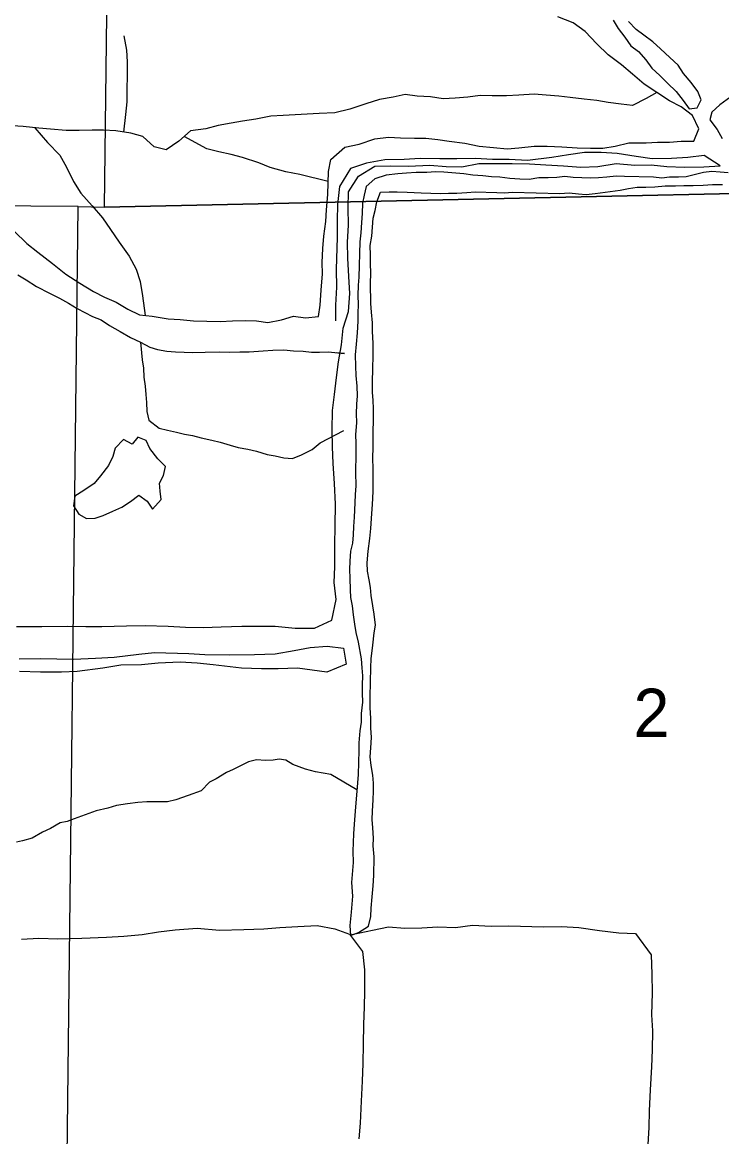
# Model space of a CAD drawing. Extents: x 0 to 34, y 0 to 22.
# Drawn here: x 2.2397 to 2.5423, y 15.0235 to 15.5055 of the extents above; entities that cross this region are included whole.
import ezdxf

# ---------------------------------------------------------------- set-up
doc = ezdxf.new("R2010")
doc.units = 0
for name, color, linetype in [('GM_X_Corporation', 7, 'Continuous'), ('GM_X_Minor_Lake', 7, 'Continuous'), ('GM_X_Minor_River', 7, 'Continuous'), ('GM_X_Section_Text', 7, 'Continuous')]:
    doc.layers.add(name, color=color, linetype=linetype)

msp = doc.modelspace()

# ---------------------------------------------------------------- linework, layer by layer
at = {"layer": 'GM_X_Corporation'}
for points in [[(2.28152, 15.93664), (2.79079, 15.94235), (2.78571, 15.43693), (2.76751, 15.43626), (2.27529, 15.42554)], [(2.76751, 15.43626), (2.75917, 15.00116), (2.25879, 14.98955), (2.26391, 15.42579), (2.27529, 15.42554)], [(2.1, 15.42693), (2.1, 14.98485), (2.25879, 14.98955), (2.26391, 15.42579)]]:
    msp.add_lwpolyline(points, close=True, dxfattribs=at)
at = {"layer": 'GM_X_Minor_Lake'}
for points in [[(2.28728, 15.32308), (2.28343, 15.32504), (2.27991, 15.32134), (2.27886, 15.31776), (2.27704, 15.31383), (2.27349, 15.30937), (2.27074, 15.30603), (2.26629, 15.30293), (2.26242, 15.30057), (2.26193, 15.2964), (2.2641, 15.29273), (2.26746, 15.29093), (2.27126, 15.29101), (2.27472, 15.29224), (2.27894, 15.29401), (2.28279, 15.2958), (2.28647, 15.29817), (2.29015, 15.30091), (2.29368, 15.29834), (2.29605, 15.29485), (2.29978, 15.29911), (2.29932, 15.30274), (2.29903, 15.30616), (2.30084, 15.30953), (2.3017, 15.31331), (2.29838, 15.31663), (2.2949, 15.3211), (2.29329, 15.32457)], [(2.29329, 15.32457), (2.28973, 15.326), (2.28728, 15.32308)]]:
    msp.add_lwpolyline(points, dxfattribs=at)
at = {"layer": 'GM_X_Minor_River'}
for points in [[(2.51419, 15.47513), (2.50879, 15.4787), (2.50379, 15.48303), (2.49897, 15.48715), (2.49321, 15.4915), (2.48822, 15.4962), (2.48324, 15.50148), (2.47803, 15.50524), (2.47146, 15.5079)], [(2.49534, 15.50645), (2.49752, 15.50278), (2.50045, 15.49908), (2.503, 15.4954), (2.50634, 15.49283), (2.50947, 15.48932), (2.51202, 15.48564), (2.51554, 15.4825), (2.51886, 15.47917), (2.52256, 15.47564), (2.52568, 15.47175), (2.52823, 15.46807), (2.53166, 15.46854), (2.53347, 15.47191), (2.53205, 15.47556), (2.52912, 15.47945), (2.52582, 15.48334), (2.52346, 15.48702), (2.51994, 15.49035), (2.51587, 15.49408), (2.51254, 15.49702), (2.50864, 15.49998), (2.50529, 15.50236), (2.50197, 15.50588)], [(2.28366, 15.49963), (2.28481, 15.49352), (2.28505, 15.48838), (2.28505, 15.48192), (2.28491, 15.47699), (2.28493, 15.4711), (2.2844, 15.4656), (2.28345, 15.45803)], [(2.2749, 15.45885), (2.26997, 15.4588), (2.26427, 15.45877), (2.25876, 15.45874), (2.25195, 15.45932), (2.24683, 15.45966), (2.24002, 15.46042), (2.233, 15.46082), (2.22696, 15.46175), (2.22186, 15.46266), (2.21693, 15.46318), (2.2107, 15.46412), (2.20503, 15.46504), (2.20016, 15.46746), (2.1969, 15.47287), (2.19514, 15.47787), (2.1951, 15.483), (2.2002, 15.48874), (2.20681, 15.48779), (2.21223, 15.48478), (2.21437, 15.47978), (2.21516, 15.47425), (2.21973, 15.4626)], [(2.28038, 15.3844), (2.28542, 15.38141), (2.29048, 15.37898), (2.29597, 15.37845), (2.30277, 15.3773), (2.30807, 15.37696), (2.31375, 15.37641), (2.32532, 15.37608), (2.33065, 15.37631), (2.33616, 15.37653), (2.34109, 15.37638), (2.34601, 15.37567), (2.35192, 15.37683), (2.35709, 15.37839), (2.3622, 15.37768), (2.36791, 15.37827), (2.36862, 15.38319), (2.369, 15.38964), (2.36957, 15.39665), (2.36952, 15.40159), (2.3697, 15.40767), (2.37023, 15.41297), (2.37098, 15.41941), (2.37131, 15.42434), (2.37188, 15.43097), (2.37217, 15.44103), (2.37326, 15.44613), (2.3793, 15.45147), (2.38541, 15.45281), (2.39231, 15.45508), (2.39822, 15.45586), (2.40333, 15.45552), (2.40941, 15.45535), (2.41434, 15.4554), (2.41945, 15.45487), (2.42437, 15.45416), (2.43118, 15.4532), (2.4374, 15.45188), (2.44365, 15.45132), (2.44952, 15.45077), (2.45447, 15.4512), (2.46114, 15.45196), (2.46683, 15.45198), (2.47309, 15.45161), (2.47972, 15.45123), (2.4856, 15.45106), (2.49092, 15.4511), (2.49626, 15.45189), (2.50218, 15.45343), (2.50959, 15.45341), (2.51453, 15.45365), (2.51966, 15.45369), (2.5248, 15.45411), (2.5303, 15.45414), (2.53235, 15.4594), (2.52967, 15.46518), (2.52484, 15.46893), (2.51979, 15.47154), (2.51419, 15.47513), (2.50957, 15.4726), (2.50378, 15.46954), (2.49886, 15.47006), (2.49319, 15.47079), (2.48828, 15.47169), (2.48279, 15.47223), (2.47673, 15.47298), (2.47181, 15.4735), (2.46632, 15.47404), (2.4612, 15.47437), (2.45455, 15.474), (2.44923, 15.47377), (2.44296, 15.47376), (2.43784, 15.47391), (2.4325, 15.47311), (2.42698, 15.4727), (2.42185, 15.47247), (2.41637, 15.4732), (2.41049, 15.47356), (2.40539, 15.47427), (2.40023, 15.47309), (2.39432, 15.47212), (2.38838, 15.4702), (2.38148, 15.46793), (2.37498, 15.46641), (2.36813, 15.46604), (2.36034, 15.46569), (2.35254, 15.46516), (2.34722, 15.46493), (2.34073, 15.4636), (2.33501, 15.46281), (2.33004, 15.46182), (2.32451, 15.46084), (2.31916, 15.45947), (2.31248, 15.45852), (2.30742, 15.45411), (2.302, 15.45028), (2.29672, 15.45157), (2.29191, 15.45608), (2.28664, 15.45756), (2.28021, 15.4585), (2.2749, 15.45885)], [(2.54622, 15.47325), (2.54157, 15.46978), (2.53806, 15.46665), (2.53721, 15.46325), (2.54032, 15.45917), (2.54248, 15.45531)], [(2.24513, 15.45985), (2.25064, 15.45347), (2.25599, 15.44799), (2.25888, 15.44278), (2.26193, 15.43661), (2.26501, 15.43158), (2.26999, 15.42612), (2.27439, 15.42086), (2.27786, 15.41582), (2.28169, 15.41039), (2.28588, 15.40438), (2.28895, 15.39879), (2.2907, 15.39342), (2.29166, 15.38712), (2.29283, 15.37875)], [(2.37204, 15.4367), (2.35979, 15.43968), (2.35375, 15.4408), (2.34697, 15.44271), (2.34209, 15.44475), (2.33494, 15.44705), (2.33004, 15.44833), (2.32475, 15.44943), (2.31948, 15.45072), (2.30974, 15.45613)], [(2.50475, 15.44367), (2.51178, 15.44385), (2.5186, 15.44308), (2.52618, 15.44286), (2.53454, 15.443), (2.54158, 15.44337), (2.53468, 15.44794), (2.52763, 15.447), (2.5206, 15.44663), (2.51224, 15.44649), (2.50524, 15.44746), (2.49712, 15.44883), (2.49011, 15.44922), (2.48289, 15.44924), (2.47602, 15.44811), (2.46878, 15.44699), (2.4583, 15.44577), (2.45034, 15.44619), (2.44313, 15.44621), (2.43573, 15.44661), (2.42776, 15.44646), (2.42035, 15.44648), (2.41181, 15.44654), (2.40497, 15.44617), (2.39661, 15.44603), (2.38859, 15.44455), (2.38169, 15.44228), (2.37691, 15.43444), (2.37612, 15.42667), (2.37593, 15.41984), (2.37591, 15.41262), (2.37551, 15.39857), (2.37568, 15.39097), (2.37527, 15.38319), (2.37526, 15.37635)], [(2.23727, 15.24411), (2.2481, 15.24418), (2.2593, 15.24424), (2.26727, 15.2442), (2.27411, 15.24419), (2.28475, 15.24445), (2.29291, 15.2446), (2.30278, 15.24431), (2.31036, 15.2439), (2.31795, 15.24369), (2.32574, 15.24403), (2.33467, 15.24434), (2.3491, 15.24431), (2.35781, 15.24349), (2.36616, 15.24343), (2.37366, 15.24683), (2.37544, 15.2559), (2.3747, 15.26314), (2.37489, 15.26997), (2.37496, 15.27928), (2.37501, 15.28764), (2.37528, 15.29713), (2.37478, 15.30607), (2.37426, 15.31463), (2.3739, 15.32186), (2.37373, 15.32928), (2.37397, 15.33763), (2.37473, 15.34445), (2.3757, 15.35183), (2.37647, 15.35865), (2.37781, 15.36602), (2.37859, 15.37321), (2.38088, 15.38037), (2.38148, 15.38814), (2.38093, 15.39556), (2.38059, 15.40355), (2.38041, 15.4104), (2.38081, 15.4178), (2.38064, 15.42521), (2.38084, 15.43223), (2.38521, 15.43895), (2.39217, 15.44331), (2.3992, 15.44348), (2.40678, 15.44327), (2.4161, 15.44376), (2.42311, 15.44317), (2.42993, 15.44298), (2.43719, 15.44448), (2.44403, 15.44447), (2.45162, 15.44444), (2.45921, 15.44422), (2.46622, 15.44383), (2.4738, 15.44342), (2.48138, 15.44282), (2.48879, 15.44318), (2.49661, 15.44448), (2.50475, 15.44367)], [(2.5451, 15.44042), (2.54169, 15.44071), (2.53809, 15.441), (2.53447, 15.44053), (2.53045, 15.43951), (2.52701, 15.43866), (2.52359, 15.43857), (2.51979, 15.43849), (2.51636, 15.43802), (2.51277, 15.4385), (2.50025, 15.43886), (2.49665, 15.43896), (2.49265, 15.43851), (2.48903, 15.43823), (2.48561, 15.43814), (2.47803, 15.43836), (2.47443, 15.43884), (2.471, 15.43837), (2.4672, 15.43829), (2.46321, 15.43822), (2.45902, 15.43758), (2.45503, 15.43769), (2.45068, 15.43801), (2.44633, 15.43852), (2.44272, 15.43862), (2.43894, 15.43911), (2.43458, 15.43942), (2.4308, 15.43991), (2.4255, 15.44045), (2.42209, 15.44073), (2.41848, 15.44084), (2.41468, 15.44057), (2.41012, 15.44051), (2.40594, 15.44025), (2.40213, 15.43998), (2.39718, 15.43936), (2.3922, 15.4378), (2.3885, 15.43448), (2.38763, 15.43071), (2.38696, 15.42731), (2.38683, 15.42275), (2.38654, 15.41896), (2.38622, 15.41441), (2.38573, 15.41062), (2.38529, 15.39525), (2.385, 15.39184), (2.38488, 15.38728), (2.38496, 15.38348), (2.38485, 15.37968), (2.38494, 15.37626), (2.38461, 15.37114), (2.38409, 15.36622), (2.38377, 15.36167), (2.38381, 15.35672)], [(2.39151, 15.32687), (2.39173, 15.33484), (2.39165, 15.33845), (2.39155, 15.34187), (2.39128, 15.34549), (2.39119, 15.3491), (2.3914, 15.35651), (2.39152, 15.36049), (2.3915, 15.36676), (2.39127, 15.37171), (2.39118, 15.37551), (2.39074, 15.38008), (2.39047, 15.38389), (2.39034, 15.39263), (2.39046, 15.39681), (2.3904, 15.40137), (2.39031, 15.40479), (2.39024, 15.40898), (2.39092, 15.41295), (2.39122, 15.41693), (2.39152, 15.42072), (2.39238, 15.42411), (2.39306, 15.42789), (2.39469, 15.43202), (2.39849, 15.43211), (2.40191, 15.4322), (2.40627, 15.43207), (2.41234, 15.43171), (2.42068, 15.43146), (2.4241, 15.43156), (2.42771, 15.43164), (2.43209, 15.4319), (2.4357, 15.43217), (2.445, 15.4319), (2.44841, 15.43181), (2.45184, 15.43209), (2.47232, 15.4315), (2.47632, 15.43176), (2.48029, 15.43127), (2.4837, 15.43098), (2.48751, 15.43144), (2.49837, 15.43284), (2.502, 15.43368), (2.50581, 15.43414), (2.50942, 15.43423), (2.51341, 15.4343), (2.51779, 15.43475), (2.52235, 15.4348), (2.52596, 15.43489), (2.52995, 15.43496), (2.53431, 15.43503), (2.53831, 15.43529), (2.54268, 15.43536)], [(2.23626, 15.41512), (2.24161, 15.40984), (2.24644, 15.40609), (2.25276, 15.40116), (2.25851, 15.39662), (2.26467, 15.39265), (2.27045, 15.38906), (2.27532, 15.38664), (2.28038, 15.3844)], [(2.23781, 15.39627), (2.24136, 15.39408), (2.24583, 15.39129), (2.25144, 15.38828), (2.25575, 15.38625), (2.25967, 15.38405), (2.2634, 15.38166), (2.27014, 15.37824), (2.2739, 15.3768), (2.27744, 15.37442), (2.28211, 15.37182), (2.28659, 15.36922), (2.2909, 15.36719), (2.29482, 15.36499), (2.29821, 15.36394), (2.30218, 15.36326), (2.30597, 15.36296), (2.31355, 15.36274), (2.31887, 15.36278), (2.32514, 15.36298), (2.32931, 15.36286), (2.33387, 15.36291), (2.33786, 15.36299), (2.34395, 15.36338), (2.34813, 15.36364), (2.35288, 15.36389), (2.35705, 15.36339), (2.36122, 15.36327), (2.36481, 15.36278), (2.36823, 15.36287), (2.37203, 15.36295), (2.37917, 15.36231), (2.37558, 15.3626)], [(2.29089, 15.3672), (2.29163, 15.35957), (2.2921, 15.35595), (2.29236, 15.35195), (2.29282, 15.34814), (2.2931, 15.34452), (2.29338, 15.34109), (2.29365, 15.3371), (2.29449, 15.33346), (2.29895, 15.32991), (2.30253, 15.32905), (2.30649, 15.32818), (2.30989, 15.32732), (2.31329, 15.32684), (2.31706, 15.32578), (2.32177, 15.3247), (2.32536, 15.32383), (2.32969, 15.32257), (2.33307, 15.32152), (2.33723, 15.32083), (2.341, 15.31996), (2.34571, 15.3185), (2.34911, 15.31802), (2.35288, 15.31715), (2.35667, 15.31685), (2.36051, 15.31845), (2.36514, 15.32079), (2.36863, 15.32354), (2.37889, 15.329)], [(2.38381, 15.35672), (2.38408, 15.35273), (2.38452, 15.34816), (2.38459, 15.34397), (2.3843, 15.34037), (2.38418, 15.3362), (2.38426, 15.33239), (2.38392, 15.32708), (2.38401, 15.32347), (2.38407, 15.31891), (2.38383, 15.31075), (2.38405, 15.30504), (2.38375, 15.30125), (2.38365, 15.29764), (2.38328, 15.29139), (2.38298, 15.28741), (2.38288, 15.2838), (2.38259, 15.2802), (2.38173, 15.2768), (2.38141, 15.27244), (2.38131, 15.26884), (2.38139, 15.26503), (2.38163, 15.26009), (2.38173, 15.25666), (2.38238, 15.25304), (2.38284, 15.24922), (2.38349, 15.24521), (2.38395, 15.24159), (2.38497, 15.23738), (2.38629, 15.23013), (2.38656, 15.22632), (2.38684, 15.22289), (2.38672, 15.2189), (2.38681, 15.21529), (2.38689, 15.21149), (2.38637, 15.20657), (2.38627, 15.20277), (2.38578, 15.19898), (2.38525, 15.19387), (2.38534, 15.19045), (2.38505, 15.1802), (2.38476, 15.1766), (2.38447, 15.17299), (2.38389, 15.16617), (2.3833, 15.15859), (2.38299, 15.15442), (2.38278, 15.14702), (2.38283, 15.14208), (2.3822, 15.13336), (2.3826, 15.12745), (2.38203, 15.12063), (2.38148, 15.11476), (2.38174, 15.11057), (2.38519, 15.1118), (2.38945, 15.11453), (2.39052, 15.11868), (2.39062, 15.12228), (2.39114, 15.12721), (2.39146, 15.13195), (2.39178, 15.1365), (2.39201, 15.14447), (2.39157, 15.14923), (2.39167, 15.15265), (2.39142, 15.15703), (2.39114, 15.16064), (2.39124, 15.16425), (2.39157, 15.16918), (2.39168, 15.17298), (2.39159, 15.1764), (2.39131, 15.17983), (2.39067, 15.18402), (2.39021, 15.18784), (2.3905, 15.19163), (2.39082, 15.19618), (2.39056, 15.20037), (2.39049, 15.20436), (2.39024, 15.20911), (2.39018, 15.21368), (2.39055, 15.22639), (2.39065, 15.23019), (2.39139, 15.23606), (2.39192, 15.24136), (2.39259, 15.24476), (2.39196, 15.24953), (2.39131, 15.25316), (2.39067, 15.25755), (2.39039, 15.26097), (2.38973, 15.26441), (2.38907, 15.26804), (2.38899, 15.27165), (2.38932, 15.27677), (2.39005, 15.28226), (2.39055, 15.28662), (2.39092, 15.29307), (2.39122, 15.29686), (2.39157, 15.30255), (2.39153, 15.30768), (2.39148, 15.31243), (2.39142, 15.31699), (2.39155, 15.32173), (2.39151, 15.32687)], [(2.2384, 15.23021), (2.24751, 15.23033), (2.25472, 15.23012), (2.26193, 15.2301), (2.27144, 15.2304), (2.27942, 15.23093), (2.29009, 15.23214), (2.29695, 15.23289), (2.31174, 15.23246), (2.31875, 15.23207), (2.32919, 15.23196), (2.34021, 15.23202), (2.34914, 15.23234), (2.35734, 15.23381), (2.36422, 15.23513), (2.37164, 15.23568), (2.37863, 15.23472), (2.37977, 15.22784), (2.37151, 15.22447), (2.35883, 15.22617), (2.35047, 15.22584), (2.34326, 15.22586), (2.33453, 15.22611), (2.32224, 15.2276), (2.31542, 15.22837), (2.30803, 15.22877), (2.29852, 15.22829), (2.29129, 15.22755), (2.28236, 15.22742), (2.27454, 15.22613), (2.26349, 15.22474), (2.25665, 15.22436), (2.24754, 15.22444), (2.23843, 15.2247)], [(2.38451, 15.17346), (2.37327, 15.1802), (2.36662, 15.18131), (2.36225, 15.18243), (2.35673, 15.1845), (2.35369, 15.18639), (2.35084, 15.18676), (2.34818, 15.18637), (2.34496, 15.18616), (2.34097, 15.18653), (2.33756, 15.18557), (2.33472, 15.18423), (2.33093, 15.18231), (2.32809, 15.18097), (2.32355, 15.17829), (2.32071, 15.17676), (2.31712, 15.17314), (2.31144, 15.17103), (2.30614, 15.16911), (2.30253, 15.16834), (2.29361, 15.1683), (2.28963, 15.1681), (2.28527, 15.16751), (2.28053, 15.16673), (2.27674, 15.16557), (2.27162, 15.16442), (2.26537, 15.16211), (2.26214, 15.16096), (2.25911, 15.15981), (2.25608, 15.15923), (2.25192, 15.15674), (2.24851, 15.15521), (2.24397, 15.15253), (2.2398, 15.15138), (2.23714, 15.1508)], [(2.23931, 15.10898), (2.24692, 15.10933), (2.25507, 15.10909), (2.26552, 15.10936), (2.27617, 15.10982), (2.28358, 15.11017), (2.29157, 15.11089), (2.29863, 15.11202), (2.30587, 15.11295), (2.31538, 15.11362), (2.32504, 15.11278), (2.33549, 15.11304), (2.34423, 15.11336), (2.35108, 15.11393), (2.35888, 15.11446), (2.36724, 15.11479), (2.37499, 15.11343), (2.38122, 15.11104), (2.38686, 15.10358), (2.38777, 15.09558), (2.3877, 15.08646), (2.38769, 15.07962), (2.38729, 15.07204), (2.38723, 15.06349), (2.387, 15.05514), (2.38678, 15.04754), (2.38634, 15.03882), (2.38588, 15.02933), (2.38531, 15.02251)], [(2.38152, 15.11074), (2.39817, 15.11428), (2.40518, 15.1137), (2.41259, 15.11386), (2.41943, 15.11423), (2.42721, 15.11401), (2.43445, 15.11494), (2.4426, 15.11452), (2.4502, 15.11468), (2.46519, 15.11424), (2.47298, 15.1144), (2.48056, 15.11399), (2.48944, 15.1126), (2.49777, 15.1116), (2.50497, 15.11139), (2.51173, 15.10207), (2.51206, 15.09371), (2.51222, 15.08572), (2.51195, 15.07623), (2.51231, 15.06919), (2.51227, 15.06102), (2.51187, 15.05363), (2.5114, 15.04376), (2.51095, 15.03466), (2.51075, 15.02744), (2.51035, 15.02005)]]:
    msp.add_lwpolyline(points, dxfattribs=at)

# ---------------------------------------------------------------- texts
at = {"layer": 'GM_X_Section_Text'}
msp.add_text('2', height=0.02093, rotation=0, dxfattribs=at).set_placement((2.50413, 15.19633))

doc.saveas('drawing.dxf')
